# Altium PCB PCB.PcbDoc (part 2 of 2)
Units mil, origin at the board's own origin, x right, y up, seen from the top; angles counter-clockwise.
Board outline 2952.76 x 1850.39 mil, 2 copper layers (Top Layer, Bottom Layer), stack 21 mil thick; 67 components, 133 nets, 435 pads, 333 vias.
Unrouted connection lines stored in the file: 207.
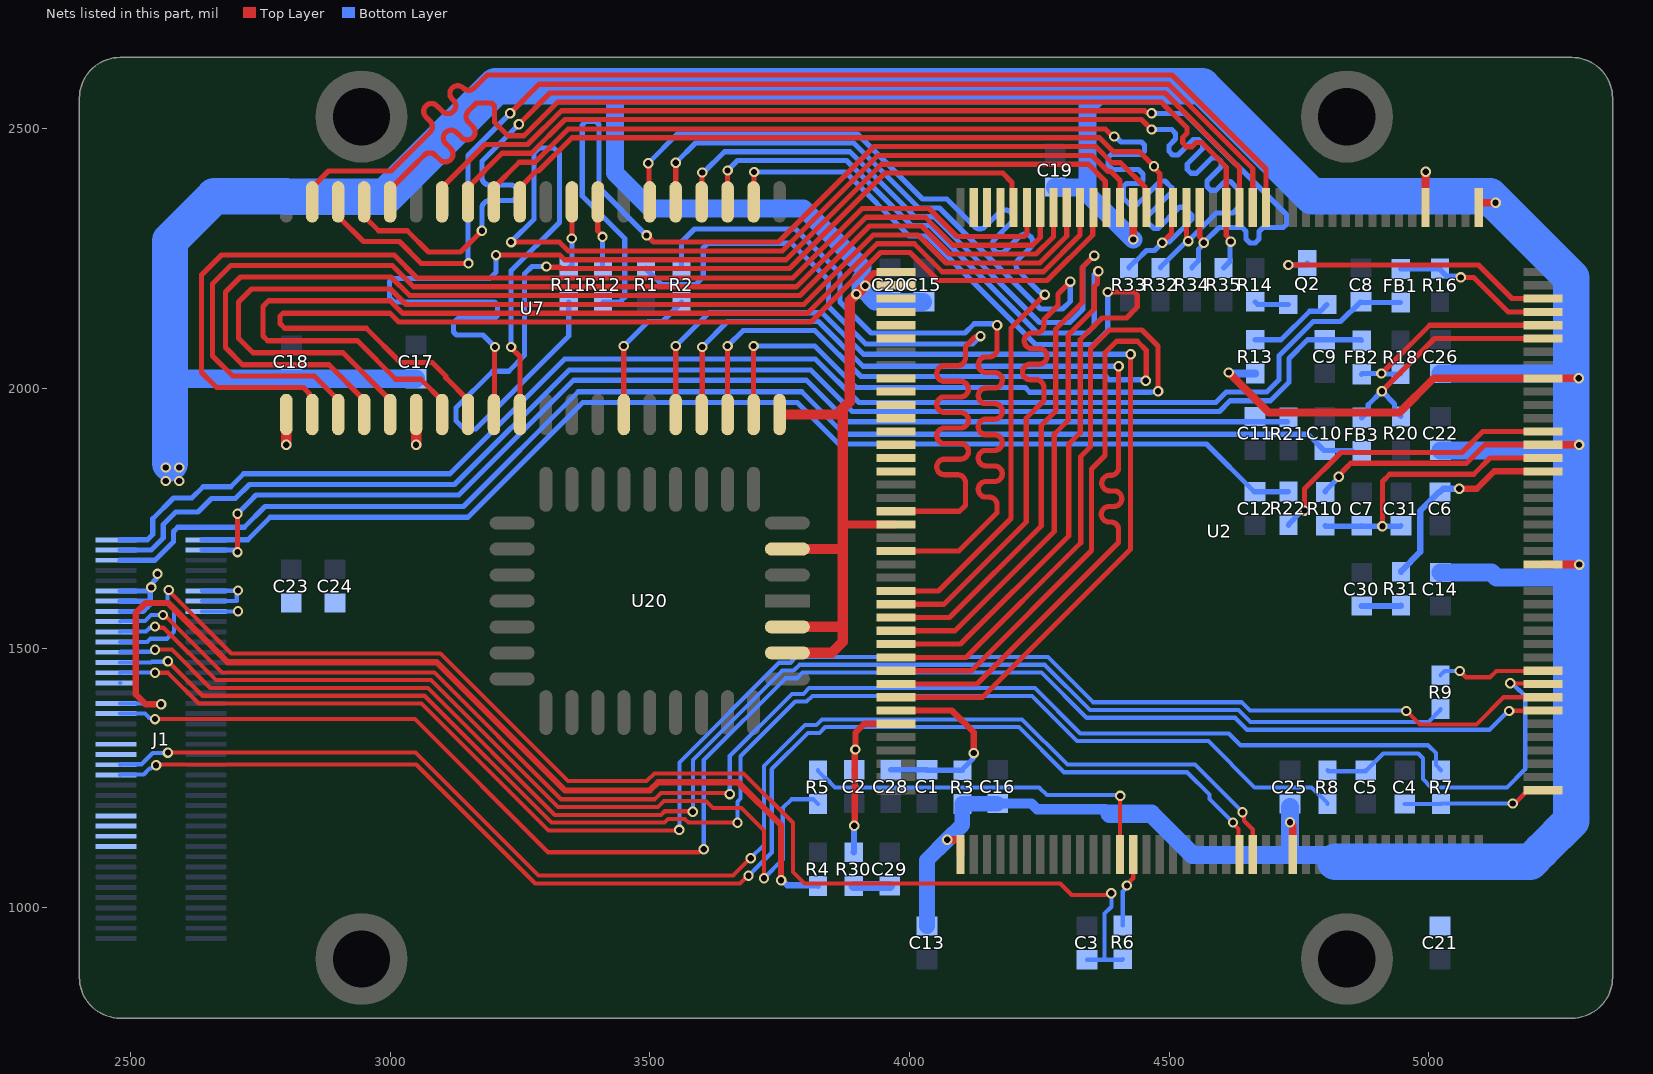
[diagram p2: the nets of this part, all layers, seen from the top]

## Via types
v1: diameter 20, hole 12, Top Layer to Bottom Layer, tented both sides, 331 vias
v2: diameter 27.56, hole 27.56, Top Layer to Bottom Layer, 2 vias

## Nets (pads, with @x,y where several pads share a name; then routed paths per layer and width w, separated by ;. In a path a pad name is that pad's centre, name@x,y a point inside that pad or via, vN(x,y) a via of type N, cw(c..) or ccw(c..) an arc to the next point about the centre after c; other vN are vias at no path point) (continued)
HSYNC1: C11.1 J1.78 R21.2 | length 2305.3
  Top Layer w10: v1(2706,1685) v1(2706,1759)
  Bottom Layer w10: J1.78@2637.8,1688.98 2699.32,1688.98 2703.29,1685 v1(2706,1685) ; v1(2706,1759) 2728.59,1781.59 2742,1795 3132.19,1795 3353.19,2016 3801.81,2016 3881.81,1936 4655.75,1936 R21.2@4727.9,1936
IOCS16#: J1.33 U2.22 | length 2613
  Top Layer w8: v1(2549.35,1274.65) 2550.76,1276.06 3050.37,1276.06 3279.43,1047 3673.89,1047 3688.69,1061.8 v1(3690.2,1061.8) ; v1(4623.29,1164.23) 4623.29,1162.47 4633.99,1151.76 4633.99,1104.2 U2.22@4635.83,1102.36
  Bottom Layer w8: J1.33@2480.31,1255.91 2481.24,1256.83 2525.61,1256.83 2536.79,1268 2539.45,1268 2546.1,1274.65 v1(2549.35,1274.65) ; v1(3690.2,1061.8) 3735,1106.6 3735,1267 3805,1337 3826.96,1337 3837.96,1348 4211,1348 4298,1261 4534.96,1261 4577.98,1217.99 4577.98,1209.54 v1(4623.29,1164.23)
IOR#: J1.55 R8.2 | length 2718.4
  Top Layer w8: v1(2572,1474.88) 2638.42,1408.46 3066.45,1408.46 3310.92,1164 3528.12,1164 3535.12,1171 3567.3,1171 3574.3,1164 v1(3669,1164)
  Bottom Layer w8: J1.55@2480.31,1472.44 2539.73,1472.44 2541.3,1474.02 v1@2571,1474.02 ; v1(3669,1164) 3669,1204.3 3675,1210.3 3675,1291.85 3780.15,1397 3802.11,1397 3813.11,1408 4235.85,1408 4322.85,1321 4576,1321 4665,1232 4774.5,1232 4805,1201.5 R8.2@4805,1200
IORDY: J1.45 U2.47 | length 3153.8
  Top Layer w8: v1(2547.24,1363.46) 3047.81,1363.46 3304.28,1107 3594.75,1107 3600.75,1113 v1(3604,1113) ; v1(5155,1379) 5155.46,1379.46 5220.01,1379.46 U2.47@5220.47,1379.92
  Bottom Layer w8: J1.45@2480.31,1374.02 2528,1374.02 2536.26,1365.76 2544.95,1365.76 v1(2547.24,1363.46) ; v1(3604,1113) 3604,1284.49 3761.51,1442 3783.47,1442 3794.47,1453 4254.49,1453 4341.49,1366 4627.49,1366 4650.49,1343 5117.36,1343 v1@5153.36,1379
IOW#: J1.57 R9.2 | length 2911.5
  Top Layer w8: v1(2547.24,1497.16) 2579.84,1497.16 2653.54,1423.46 3072.67,1423.46 3317.13,1179 3521.91,1179 3528.91,1186 3582,1186 v1(3583,1185)
  Bottom Layer w8: J1.57@2480.31,1492.13 2481.24,1493.05 v1@2548.03,1493.05 ; v1(3583,1185) 3583,1284.71 3755.29,1457 3777.26,1457 3788.26,1468 4260.71,1468 4347.71,1381 4633.71,1381 4656.71,1358 4999.6,1358 5023.1,1381.5 R9.2@5023.1,1383
IREF: Q2.C U2.78 | length 555.5
  Top Layer w10: v1(4730,2238) 5096,2238 5160.77,2173.23 U2.78@5220.47,2173.23
  Bottom Layer w10: v1(4730,2238) 4762.5,2238 Q2.C@4766.5,2242
LA20: J1.25
LA21: J1.23
LA22: J1.21
LA23: J1.19
MCS16#: J1.35 U2.23 | length 2647.2
  Top Layer w8: v1(2572,1299) 3048.64,1299 3285.64,1062 3660.7,1062 v1(3694.35,1095.65) ; v1(4641.51,1184.15) 4643.81,1181.85 4643.81,1173.95 4644.55,1173.21 4644.55,1167.75 4661.21,1151.09 4661.21,1102.57 U2.23@4661.42,1102.36
  Bottom Layer w8: J1.35@2480.31,1275.59 2481.24,1276.51 2521.51,1276.51 2542.9,1297.9 2570.9,1297.9 v1(2572,1299) ; v1(3694.35,1095.65) 3720,1121.3 3720,1273.21 3798.79,1352 3820.75,1352 3831.75,1363 4217.21,1363 4304.21,1276 4550.2,1276 4641.51,1184.69 v1(4641.51,1184.15)
MD0: U2.136
MD1: U2.135
MD2: U2.134
MD3: U2.133
MD4: U2.132
MD5: U2.131
MD6: U2.130
MD7: U2.129
MD8: U2.126
MD9: U2.125
MD10: U2.124
MD11: U2.123
MD12: U2.122
MD13: U2.119
MD14: U2.118
MD15: U2.117
MD16: U2.115 U7.2 | length 2208.3
  Top Layer w10: U7.2@2850,1950 2850,1981.79 2844.41,1987.38 2844.41,1990.59 2833,2002 2666,2002 2637,2031 2637,2219 2675,2257 3008,2257 3052,2213 3775.34,2213 3909.34,2347 4037.6,2347 4091.6,2293 4220.52,2293 4226.38,2298.86 U2.115@4226.38,2348.43
MD17: U2.114 U7.3 | length 2211.2
  Top Layer w10: U7.3@2900,1950 2900,1978 2854,2024 2697,2024 2658,2063 2658,2202 2693,2237 3003.96,2237 3044.96,2196 3782.38,2196 3916.38,2330 4030.56,2330 4084.56,2276 4237.04,2276 4251.97,2290.93 U2.114@4251.97,2348.43
MD18: U2.113 U7.4 | length 2213
  Top Layer w10: U7.4@2950,1950 2950,1978 2882,2046 2716,2046 2683,2079 2683,2186 2712,2215 3001.92,2215 3037.92,2179 3789.42,2179 3923.42,2313 4023.52,2313 4077.52,2259 4244.08,2259 4277.56,2292.48 U2.113@4277.56,2348.43
MD19: U2.112 U7.5 | length 2211
  Top Layer w10: U7.5@3000,1950 3000,1978 2909,2069 2736,2069 2708,2097 2708,2167 2733,2192 3000.88,2192 3030.88,2162 3796.46,2162 3930.46,2296 4016.48,2296 4070.48,2242 4251.12,2242 4303.15,2294.02 U2.112@4303.15,2348.43
MD20: U2.111 U7.7 | length 2228.6
  Top Layer w10: U7.7@3100,1950 3100,1977 3059,2018 3011,2018 2937,2092 2764.25,2092 2755,2101.25 2755,2158.25 2765.75,2169 2999.83,2169 3023.83,2145 3803.5,2145 3937.5,2279 4009.44,2279 4063.44,2225 4258.17,2225 4328.74,2295.57 U2.111@4328.74,2348.43
MD21: U2.110 U7.8 | length 2208.7
  Top Layer w10: U7.8@3150,1950 3150,1978 3107,2021 3107,2024 3081,2050 3020,2050 2954,2116 2797,2116 2788,2125 2788,2139.14 2793.86,2145 2999.79,2145 3016.79,2128 3810.54,2128 3944.54,2262 4001,2262 4055,2208 4265.21,2208 4353.23,2296.02 4353.23,2347.33 U2.110@4354.33,2348.43
MD22: U2.109 U7.9 | length 2159.7
  Top Layer w10: U7.9@3200,1950 3201,1951 3201,2079 v1(3202,2080) ; v1(3204,2257) 3326.85,2257 3335.85,2248 3762.25,2248 3946.25,2432 4344.76,2432 4377.05,2399.72 4377.05,2351.3 U2.109@4379.92,2348.43
  Bottom Layer w10: v1(3202,2080) 3178.86,2103.14 3127.86,2103.14 3122,2109 3122,2126 3131,2135 3201.14,2135 3207,2140.86 3207,2161 3201,2167 3008,2167 2999,2176 2999,2206.14 3004.86,2212 3192,2212 3204,2224 v1(3204,2257)
MD23: U2.108 U7.10 | length 2123.4
  Top Layer w10: v1(3233,2080) 3233,2078.64 3250,2061.64 U7.10@3250,1950 ; v1(3233,2282) 3325.89,2282 3342.89,2265 3755.21,2265 3939.21,2449 4351.8,2449 4382.8,2418 4388.34,2418 4405.51,2400.83 U2.108@4405.51,2348.43
  Bottom Layer w10: v1(3233,2080) 3233,2227 3326,2320 3326,2452.4 3315,2463.4 3287,2463.4 3277,2453.4 3277,2326 v1(3233,2282)
MD24: U2.105 U7.31 | length 1395.6
  Top Layer w10: U7.31@3250,2359.45 3250,2387.45 3281.55,2419 3286,2419 3350,2483 4365.89,2483 4392.89,2456 4443,2456 v1(4471,2428) 4471,2425.29 4482.28,2414.01 U2.105@4482.28,2348.43
MD25: R33.2 U2.104 U7.32 | length 2161.7
  Top Layer w10: U7.32@3200,2359.45 3200,2387.45 3248.55,2436 3278.96,2436 3342.96,2500 4377.29,2500 4391.79,2485.5 v1(4394.5,2485.5) ; v1(4487,2281) 4505,2299 4505,2345.55 U2.104@4507.87,2348.43
  Bottom Layer w10: v1(4394.5,2485.5) 4397.21,2485.5 4407.71,2475 4447.14,2475 4453,2469.14 4453,2456.86 4447.14,2451 4388.86,2451 4383,2445.14 4383,2430 4391,2422 4441,2422 4450,2413 4450,2400.86 4444.14,2395 4417.86,2395 4412,2389.14 4412,2367 4424,2355 4439,2355 4483.86,2399.86 4492.14,2399.86 4505.36,2386.64 4505.36,2378.36 4457.14,2330.14 4457.14,2321.86 4470.86,2308.14 4479.14,2308.14 4520.36,2349.36 4528.64,2349.36 4543.86,2334.14 4543.86,2325.86 4500.68,2282.68 4488.68,2282.68 4471.82,2265.82 4456.82,2265.82 4437,2246 4435.5,2246 4423,2233.5 R33.2@4423,2232
MD26: R32.2 U2.103 U7.33 | length 2160.8
  Top Layer w10: U7.33@3150,2359.45 3150,2387.45 3215.55,2453 3271.92,2453 3336.92,2518 4447,2518 4466.11,2498.89 v1(4466.5,2498.89) ; U2.103@4533.46,2348.43 4533.46,2290.24 4537,2286.71 v1(4537,2284)
  Bottom Layer w10: v1(4466.5,2498.89) 4488.45,2498.89 4505.27,2498.89 4512.77,2491.39 4512.77,2480.78 4499.76,2467.77 4499.76,2457.17 4506.83,2450.1 4517.44,2450.1 4546.85,2479.5 4557.45,2479.5 4564.52,2472.43 4564.52,2461.83 4535.11,2432.42 4535.11,2421.81 4542.19,2414.74 4552.79,2414.74 4582.2,2444.15 4592.81,2444.15 4599.88,2437.08 4599.88,2426.47 4573.04,2399.63 4573.04,2389.02 4580.11,2381.95 4590.72,2381.95 4607.58,2398.81 4618.19,2398.81 4635,2382 4635,2366 4635,2350 4623,2338 4591,2338 v1(4537,2284) 4535.09,2282.09 4532.34,2282.09 4483.75,2233.5 R32.2@4483.75,2232
MD27: R34.2 U2.102 U7.34 | length 2160.8
  Top Layer w10: U7.34@3100,2359.45 3100,2387.45 3182.55,2470 3264.88,2470 3329.88,2535 4454.04,2535 4457.13,2531.91 4464.59,2531.91 v1(4466.5,2530) ; U2.102@4559.06,2348.43 4559.06,2291.65 4567,2283.71 v1(4567,2281)
  Bottom Layer w10: v1(4466.5,2530) 4531,2530 4726,2335 4726,2315.86 4720.14,2310 4686,2310 4681,2310 4673.5,2302.5 4673.5,2288.1 4666,2280.6 4656,2280.6 4648.5,2288.1 4648.5,2302.5 4641,2310 4628,2310 4596,2310 v1(4567,2281) 4567,2278.29 4557,2268.29 4557,2246 4544.5,2233.5 R34.2@4544.5,2232
MD28: R35.2 U2.100 U7.36 | length 2187.8
  Top Layer w10: U7.36@3000,2359.45 3000,2383.66 3041.01,2424.67 3065.76,2449.42 cw(c3076.37,2438.81) 3086.97,2449.42 3095.52,2440.87 ccw(c3106.13,2451.48) 3116.73,2440.87 ccw(c3106.13,2451.48) 3116.73,2462.08 3106.76,2472.06 cw(c3117.36,2482.67) 3106.76,2493.27 cw(c3117.36,2482.67) 3127.97,2493.27 3137.95,2483.3 ccw(c3148.55,2493.9) 3159.16,2483.3 ccw(c3148.55,2493.9) 3159.16,2504.51 3150.61,2513.06 cw(c3161.22,2523.67) 3150.61,2534.27 3166.34,2550 3167.46,2550 3195.14,2550 3201,2544.14 3201,2513 3227,2487 3257.83,2487 3322.83,2552 4485,2552 4492.56,2544.44 4513.5,2523.5 4534.71,2502.29 4534.71,2491.68 4526.31,2483.28 4526.31,2472.67 4533.38,2465.6 4543.99,2465.6 4552.39,2474 4563,2474 4599.5,2437.5 4610.24,2426.76 4610.24,2399.45 U2.100@4610.24,2348.43 4610.12,2348.31 4610.12,2294.59 4619,2285.71 v1(4619,2283)
  Bottom Layer w10: R35.2@4605.25,2232 4617.75,2244.5 4617.75,2281.75 v1(4619,2283)
MD29: U2.99 U7.37 | length 2197.4
  Top Layer w10: U7.37@2950,2359.45 2950,2332 2978,2304 3033,2304 3074,2263 3135.72,2263 v1(3176.72,2304) ; v1(3248,2509) 3308,2569 4492.04,2569 4635.83,2425.21 U2.99@4635.83,2348.43
  Bottom Layer w10: v1(3176.72,2304) 3176.72,2312 3176.72,2347 cw(c3191.72,2347) 3191.72,2362 3231.64,2362 ccw(c3231.64,2377) 3231.64,2392 3191.72,2392 cw(c3191.72,2407) 3176.72,2407 3176.72,2437.72 3217,2478 v1(3248,2509)
MD30: U2.98 U7.38 | length 2235.5
  Top Layer w10: U7.38@2900,2359.45 2900,2331.45 2948.45,2283 3018,2283 3060,2241 v1(3151,2241) ; v1(3231,2530) 3287,2586 3388.04,2586 4499.08,2586 4661.42,2423.67 U2.98@4661.42,2348.43
  Bottom Layer w10: v1(3151,2241) 3150,2242 3150,2449 v1(3231,2530)
MD31: U2.97 U7.39 | length 2202.6
  Top Layer w10: U7.39@2850,2359.45 2850,2387.45 2881.55,2419 3002,2419 3073.5,2490.5 3077.04,2494.04 ccw(c3066.43,2504.64) 3077.04,2515.25 3069.04,2523.25 cw(c3079.64,2533.85) 3069.04,2544.46 cw(c3079.64,2533.85) 3090.25,2544.46 3100.8,2533.91 ccw(c3111.4,2544.52) 3122.01,2533.91 ccw(c3111.4,2544.52) 3122.01,2555.13 3119.46,2557.68 cw(c3130.07,2568.28) 3119.46,2578.89 cw(c3130.07,2568.28) 3140.67,2578.89 ; 3140.68,2578.89 ccw(c3151.28,2589.5) 3161.89,2578.89 3187,2604 3190,2604 4506,2604 4687.01,2422.99 U2.97@4687.01,2348.43
MEMR#: J1.39
MEMW#: J1.37
NetC1_1: C1.1 C28.1 R3.2 U2.154 | length 387.1
  Top Layer w12: U2.154@3974.41,1379.92 4082.08,1379.92 4124,1338 v1(4124,1298)
  Bottom Layer w10: C28.1@3964,1266 C1.1@4034,1266 ; C1.1@4034,1265 R3.2@4102,1265 4102,1266.5 4122.09,1286.59 4122.09,1296.09 v1(4124,1298)
NetC2_1: C2.1 R30.1 U2.155 | length 356.7
  Top Layer w12: v1(3894,1158) 3895,1159 3895,1304 v1(3896,1305) 3896,1337 3913.33,1354.33 U2.155@3974.41,1354.33
  Bottom Layer w10: C2.1@3894,1266 3896,1268 v1(3896,1305)
  Bottom Layer w12: R30.1@3893,1107 3893.5,1107.5 3893.5,1157.5 v1(3894,1158)
NetC4_1: C4.1 R7.2 U2.41 | length 277.4
  Top Layer w8: v1(5162,1201) 5164.3,1203.3 5167.86,1203.3 5190.94,1226.38 U2.41@5220.47,1226.38
  Bottom Layer w8: C4.1@4954,1200 R7.2@5024,1200 5025,1201 v1(5162,1201)
NetC5_1: C5.1 R8.1 U2.49 | length 700.9
  Top Layer w8: v1(5157.11,1432.69) 5157.9,1431.89 5219.68,1431.89 U2.49@5220.47,1431.1
  Bottom Layer w8: R8.1@4805,1265 4807,1263 C5.1@4879,1263 ; C5.1@4879,1264.96 4880.5,1264.96 4912.54,1297 4980,1297 4989,1288 4989,1247.94 5004.94,1232 5151,1232 5186,1267 5186,1408 5174.92,1419.08 5173.96,1419.08 v1@5160.35,1432.69
NetC6_1: C6.1 R31.1 U2.65 | length 400.8
  Top Layer w12: v1(5059,1807) 5093,1807 5126.55,1840.55 U2.65@5220.47,1840.55
  Bottom Layer w12: R31.1@4947,1647 4947,1648.5 4984,1685.5 4984,1764.46 5020.5,1800.96 C6.1@5022,1800.96 5028.04,1807 v1(5059,1807)
NetC7_1: C7.1 C31.1 R10.1 U2.66 | length 561.4
  Top Layer w10: v1(4911,1735) 4911,1821 4925,1835 5087,1835 5118.14,1866.14 U2.66@5220.47,1866.14
  Bottom Layer w10: R10.1@4801,1736 4802,1735 4870,1735 C7.1@4871,1736 ; C7.1@4871,1735 4946,1735 C31.1@4947,1736
NetC29_1: C29.1 R30.2 | length 69
  Bottom Layer w19.68: R30.2@3893,1042 C29.1@3962,1042
NetC30_1: C30.1 R31.2 | length 76.4
  Bottom Layer w12: C30.1@4871,1581.04 4946.04,1581.04 R31.2@4947,1582
NetQ2_B: Q2.B R13.1 | length 166.7
  Bottom Layer w10: R13.1@4666,2093.97 4715.97,2093.97 4771,2149 4791.5,2149 Q2.B@4804.5,2162
NetQ2_E: Q2.E R14.2 | length 65.6
  Bottom Layer w10: R14.2@4666,2167 4671,2162 Q2.E@4729.5,2162
NetR1_2: R1.2 U2.139 | length 1695.6
  Top Layer w10: U2.139@3974.41,1763.78 4096.78,1763.78 4108,1775 4108,1814 4108,1819 ccw(c4093,1819) 4093,1834 4067.69,1834 cw(c4067.69,1849) 4067.69,1864 4098.69,1864 ccw(c4098.69,1879) 4098.69,1894 4067.69,1894 cw(c4067.69,1909) 4067.69,1924 4098.69,1924 ccw(c4098.69,1939) 4098.69,1954 4067.69,1954 cw(c4067.69,1969) 4067.69,1984 4098.69,1984 ccw(c4098.69,1999) 4098.69,2014 4067.69,2014 cw(c4067.69,2029) 4067.69,2044 4093,2044 ccw(c4093,2059) 4108,2059 4108,2080.93 4116.78,2089.71 4126.16,2099.09 4135.09,2099.09 v1(4137,2101)
  Bottom Layer w10: R1.2@3493,2232 3493,2230.5 3523.5,2200 3588,2200 3603,2215 3603,2271 3612,2280 3773,2280 3844,2209 3844,2157.96 3915.96,2086 4122,2086 v1(4137,2101)
NetR2_2: R2.2 U2.142 | length 1693.9
  Top Layer w10: U2.142@3974.41,1687.01 4095.01,1687.01 4169,1761 4169,1770.98 4169,1775.98 ccw(c4154,1775.98) 4154,1790.98 4147.54,1790.98 cw(c4147.54,1805.98) 4147.54,1820.98 4164,1820.98 ccw(c4164,1835.98) 4164,1850.98 4147.54,1850.98 cw(c4147.54,1865.98) 4147.54,1880.98 4164,1880.98 ccw(c4164,1895.98) 4164,1910.98 4147.54,1910.98 cw(c4147.54,1925.98) 4147.54,1940.98 4164,1940.98 ccw(c4164,1955.98) 4164,1970.98 4147.54,1970.98 cw(c4147.54,1985.98) 4147.54,2000.98 4164,2000.98 ccw(c4164,2015.98) 4164,2030.98 4147.54,2030.98 cw(c4147.54,2045.98) 4147.54,2060.98 4154,2060.98 ccw(c4154,2075.98) 4169,2075.98 4169,2119.77 v1(4169,2122)
  Bottom Layer w10: R2.2@3561,2232 3561,2282 3586,2307 3781,2307 3866.5,2221.5 3866.5,2166.5 3926,2107 4107.29,2107 4125,2124.71 4159.22,2124.71 4160.02,2123.91 4167.09,2123.91 v1(4169,2122)
NetR5_2: R5.2 U2.13 | length 716.7
  Top Layer w8: U2.13@4405.51,1102.36 4405.76,1102.61 4405.76,1215.26 v1(4406,1215.5)
  Bottom Layer w8: R5.2@3824,1265 3824,1263.5 3837.5,1250 3839,1250 3857,1232 4250,1232 4265,1217 4404.5,1217 v1(4406,1215.5)
NetR6_2: R6.2 U2.14 | length 144.7
  Top Layer w8: v1(4419,1043) 4419,1044.95 4431.1,1057.05 U2.14@4431.1,1102.36
  Bottom Layer w8: R6.2@4411,966 4411,1031.75 4419,1039.75 v1(4419,1043)
NetR9_1: R9.1 U2.50 | length 210.9
  Top Layer w8: v1(5060,1456) 5072,1444 5118,1444 5130.35,1456.35 5220.13,1456.35 U2.50@5220.47,1456.69
  Bottom Layer w8: R9.1@5023.1,1448 5031.1,1456 v1(5060,1456)
NetR11_1: R11.1 U2.116 | length 1799.5
  Top Layer w10: v1(3301,2235) 3302.2,2233.8 3326,2233.8 3328.8,2231 3769.29,2231 3953.29,2415 4180,2415 4197.91,2397.09 4197.91,2351.3 U2.116@4200.79,2348.43
  Bottom Layer w10: v1(3301,2235) 3273,2235 3259,2221 3259,2064 3228.49,2033.49 3197.49,2033.49 3126.91,1962.91 3126.91,1938.09 3142.91,1922.09 3165.09,1922.09 3344,2101 R11.1@3344,2167
NetR12_1: R12.1 U2.106 | length 1814.9
  Top Layer w10: v1(3494,2295) 3507,2282 3748.17,2282 3932.17,2466 4358.85,2466 4389.85,2435 4406.77,2435 4453.82,2387.95 4453.82,2351.3 U2.106@4456.69,2348.43
  Bottom Layer w10: R12.1@3410,2167 3443,2167 3452,2176 3452,2289 3370,2371 3370,2507.71 3376.86,2514.57 3396,2514.57 3402,2508.57 3402,2387 v1(3494,2295)
OSC: J1.47 R4.1 | length 1917.1
  Top Layer w12: v1(2559,1392) 2529,1392 2510,1411 2510,1568 2529.02,1587.02 2572.94,1587.02 2686.96,1473 3089.6,1473 3336.6,1226 3500,1226 3516,1242 3670,1242 3753,1159 v1(3753,1053)
  Bottom Layer w8: J1.47@2480.31,1393.7 2531.88,1393.7 2533,1392.58 2558.42,1392.58 v1(2559,1392)
  Bottom Layer w12: v1(3753,1053) 3755.16,1053 3764.66,1043.5 3824,1043.5 R4.1@3824,1042
RAS#: R2.1 U7.14 | length 279.1
  Top Layer w10: U7.14@3450,1950 v1(3450,2082)
  Bottom Layer w10: v1(3450,2082) 3497,2129 3524.5,2129 3561,2165.5 R2.1@3561,2167
REFSH#: J1.53 U2.48 | length 3158.4
  Top Layer w8: v1(2547.24,1452.6) 2572.4,1452.6 2631.54,1393.46 3060.24,1393.46 3304.71,1149 v1@3557,1149 ; v1(4957,1379) 4983,1353 5092,1353 5144.51,1405.51 U2.48@5220.47,1405.51
  Bottom Layer w8: J1.53@2480.31,1452.76 2480.44,1452.89 2549.87,1452.89 v1@2550,1453.02 ; v1(3557,1150) 3557,1279.92 3749.08,1472 3771.04,1472 3782.04,1483 4266.92,1483 4353.92,1396 4639.92,1396 4655.92,1380 4956,1380 v1(4957,1379)
RESET: J1.63 R7.1 | length 2908
  Top Layer w8: v1(2562.64,1563.92) 2565.88,1563.92 2676.33,1453.46 3085.09,1453.46 3329.56,1209 3509.48,1209 3521.48,1221 3652,1221 v1(3654,1219)
  Bottom Layer w8: J1.63@2480.31,1551.18 2481.24,1552.1 2527.92,1552.1 2539.73,1563.92 v1(2562.64,1563.92) ; v1(3654,1219) 3654,1292.07 3773.93,1412 3795.9,1412 3806.9,1423 4242.07,1423 4329.07,1336 4615.07,1336 4638.07,1313 4999,1313 5014,1298 5014,1275 R7.1@5024,1265
SMEMR#: C3.1 J1.59 R6.1 | length 2529.8
  Top Layer w8: v1(2573.9,1612) 2573.9,1610.1 2694,1490 3096.64,1490 3342.64,1244 3493.96,1244 3508.96,1259 3680.79,1259 3776,1163.79 3776,1095 3776,1068.79 3797.79,1047 3824,1047 4290.64,1047 4312.64,1025 4378.31,1025 4379.02,1025.7 4386.7,1025.7 v1(4389,1028)
  Bottom Layer w8: J1.59@2480.31,1511.81 2532.19,1511.81 2538.55,1518.16 2570.16,1518.16 2583.64,1531.64 2583.64,1573.17 2570.95,1585.86 2570.95,1592.49 2571.6,1593.14 2571.6,1609.7 v1(2573.9,1612) ; C3.1@4342,900 4376,900 ; v1(4389,1028) 4389,1002 4376,989 4376,900 ; R6.1@4411,901 4410,900 4376,900
SMEMW#: J1.61 R5.1 | length 1738
  Top Layer w8: v1(2547.24,1541.73) 2549.54,1539.44 2563.56,1539.44 2664.54,1438.46 3078.88,1438.46 3323.35,1194 3515.69,1194 3527.69,1206 3608,1206 3622,1192 3676.53,1192 3720,1148.53 v1(3720,1057)
  Bottom Layer w8: J1.61@2480.31,1531.5 2481.24,1532.42 2530.17,1532.42 2537.19,1539.44 2548.42,1539.44 v1@2549,1540.02 ; v1(3720,1057) 3756,1093 3756,1192 3773,1209 3815,1209 R5.1@3824,1200
SYSCLK: J1.51 | length 0
VA0: U2.153 U7.16 | length 2012.8
  Top Layer w10: U7.16@3550,1950 v1(3550,2082) ; U2.153@3974.41,1405.51 4141.04,1405.51 4426,1690.48 v1(4426,2066)
  Bottom Layer w10: v1(3550,2082) 3614,2146 3831.92,2146 3911.92,2066 v1(4426,2066)
VA1: U2.152 U7.17 | length 1962.8
  Top Layer w10: U7.17@3601,1948 v1(3601,2080) ; U2.152@3974.41,1431.1 4130.44,1431.1 4403,1703.67 4403,1723 4403,1728 ccw(c4388,1728) 4388,1743 4384.62,1743 cw(c4384.62,1758) 4384.62,1773 4394,1773 ccw(c4394,1788) 4394,1803 4385.61,1803 cw(c4385.61,1818) 4385.61,1833 4388,1833 ccw(c4388,1848) 4403,1848 4403,2022 v1(4403,2043)
  Bottom Layer w10: v1(3601,2080) 3650,2129 3824.88,2129 3910.88,2043 v1(4403,2043)
VA2: U2.151 U7.18 | length 2008.4
  Top Layer w10: U7.18@3650,1950 v1(3650,2082) ; U2.151@3974.41,1456.69 4119.84,1456.69 4351,1687.86 4351,1845 4377,1871 4377,2069 4399,2091 4439,2091 4456,2074 4456,2016 v1(4455,2015)
  Bottom Layer w10: v1(3650,2082) 3680,2112 3817.83,2112 3906.83,2023 4379,2023 4385.09,2016.91 4453.09,2016.91 v1(4455,2015)
VA3: U2.150 U7.19 | length 2022.3
  Top Layer w10: U7.19@3700,1950 v1(3700,2082) ; U2.150@3974.41,1482.28 4109.24,1482.28 4330,1703.05 4330,1869 4349,1888 4349,2077 4385,2113 4448,2113 4479,2082 v1(4479,1995)
  Bottom Layer w10: v1(3700,2082) 3817.84,2082 3897.84,2002 4223,2002 4232,1993 4464.29,1993 4464.38,1993.09 4477.09,1993.09 v1(4479,1995)
VA4: U2.149 U7.22 | length 1986.1
  Top Layer w10: U7.22@3700,2359.45 3700.5,2359.95 3700.5,2416.5 v1(3701,2417) ; U2.149@3974.41,1507.87 4098.64,1507.87 4307,1716.24 4307,1893 4329,1915 4329,2094 4371,2136 4418,2136 4439,2157 4439,2180.14 4433.14,2186 v1(4382,2186)
  Bottom Layer w10: v1(3701,2417) 3876.83,2417 3999.83,2294 4034,2294 4243,2085 4355,2085 4382,2112 v1(4382,2186)
VA5: U2.148 U7.23 | length 1947.4
  Top Layer w10: U7.23@3650,2359.45 v1(3650,2420) ; U2.148@3974.41,1533.47 4088.04,1533.47 4279,1724.43 4279,1912 4306,1939 4306,2103 4356,2153 4356,2196 4362.09,2202.09 4362.09,2224.09 v1(4364,2226)
  Bottom Layer w10: v1(3650,2420) 3669,2439 3878.88,2439 4003.92,2313.96 4039.77,2313.96 4246.72,2107 4342,2107 4356,2121 4356,2219.57 4362.43,2226 v1(4364,2226)
VA6: U2.147 U7.24 | length 1981.6
  Top Layer w10: U7.24@3600,2359.45 3600.5,2359.95 3600.5,2415.5 v1(3601,2416) ; U2.147@3974.41,1559.06 4077.44,1559.06 4254,1735.62 4254,1929 4282,1957 4282,2115 4333,2166 4333,2233 v1(4356,2256)
  Bottom Layer w10: v1(3601,2416) 3603.71,2416 3643.71,2456 3885.92,2456 4010.96,2330.96 4046.81,2330.96 4250.76,2127 4309,2127 4334,2152 4334,2234 v1(4356,2256)
VA7: U2.146 U7.25 | length 1960.8
  Top Layer w10: U7.25@3550,2359.45 v1(3550,2435) ; U2.146@3974.41,1584.65 4066.84,1584.65 4225,1742.81 4225,1943 4259,1977 4259,1997 4259,2002 ccw(c4244,2002) 4244,2017 4232.95,2017 cw(c4232.95,2032) 4232.95,2047 4250,2047 ccw(c4250,2062) 4250,2077 4236.17,2077 cw(c4236.17,2092) 4236.17,2107 4244,2107 ccw(c4244,2122) 4259,2122 4259,2133 4286,2160 4286,2182 v1(4310,2206)
  Bottom Layer w10: v1(3550,2435) 3588,2473 3892.96,2473 4018,2347.96 4057.81,2347.96 4252.76,2153 4295,2153 4310,2168 v1(4310,2206)
VA8: U2.145 U7.26 | length 1951.3
  Top Layer w10: v1(3497,2434) 3498.5,2432.5 3498.5,2360.95 U7.26@3500,2359.45 ; U2.145@3974.41,1610.24 4056.24,1610.24 4196,1750 4196,2116 v1(4261,2181)
  Bottom Layer w10: v1(3497,2434) 3553,2490 3900,2490 4025.04,2364.96 4071.92,2364.96 4121.44,2315.44 4124.97,2311.9 ccw(c4135.58,2322.51) 4146.19,2311.9 4173.73,2339.45 cw(c4184.34,2328.84) 4194.95,2339.45 cw(c4184.34,2328.84) 4194.95,2318.23 4163.86,2287.15 ccw(c4174.47,2276.55) 4163.86,2265.94 ccw(c4174.47,2276.55) 4185.08,2265.94 4212.11,2292.98 cw(c4222.72,2282.37) 4233.33,2292.98 cw(c4222.72,2282.37) 4233.33,2271.76 4209.83,2248.26 ccw(c4220.43,2237.66) 4209.83,2227.05 4250.88,2186 4253.29,2186 4254.62,2184.68 4258.29,2181 v1(4261,2181)
VCC: C13.1 C14.1 C15.1 C16.1 C17.1 C18.1 C19.1 C20.1 C21.1 C22.1 C23.1 C24.1 C25.1 C26.1 J1.65 J1.66 J1.67 J1.68 J1.69 J1.70 R3.1 R10.2 R13.2 U2.1 U2.26 U2.58 U2.67 U2.72 U2.81 U2.85 U2.107 U2.121 U2.140 U7.1 U7.6 U7.20 U20.3 U20.31 U20.32 | length 12322.5
  Top Layer w10: v1(4827,1830) 4827,1832.71 4842.93,1848.63 4842.93,1848.93 4850,1856 5073,1856 5108.73,1891.73 U2.67@5220.47,1891.73 ; U2.58@5220.47,1661.42 U2.58@5220.68,1661.21 ; v1@5289.79,1661.21 v1(5290,1661)
  Top Layer w12: v1@3915.83,2201.7 3916.53,2201.7 3919,2204.16 3919,2210 3931.53,2222.53 3972.54,2222.53 U2.121@3974.41,2224.41
  Top Layer w15: 3872,1736 3874.19,1738.19 U2.140@3974.41,1738.19 ; v1(4073,1131) 4098.05,1131 4098.43,1130.63 U2.1@4098.43,1102.36 ; v1(4431,2287) 4431.05,2287.05 U2.107@4431.1,2348.43 U2.107@4431.1,2348.43 ; v1(4615,2031) 4692,1954 4944,1954 5009.68,2019.69 U2.72@5220.47,2019.69 5220.63,2019.84 5288.84,2019.84 v1(5289,2020) ; v1(4733,1165) 4733,1163.65 4738.19,1158.46 U2.26@4738.19,1102.36 ; U2.85@4994.09,2348.43 v1@4994.09,2417.54 ; U2.81@5096,2359 5097,2358 v1(5129,2358) ; U2.67@5220.47,1891.73 v1@5289.58,1891.73 ; U2.58@5220.68,1661.21 v1@5289.79,1661.21
  Top Layer w20: v1(2800,1892) U7.1@2800,1950 ; v1(3050,1892) U7.6@3050,1950 ; U7.20@3750,1950 3860.28,1950 3872,1961.72 ; U20.31@3765,1491 3850.28,1491 3872,1512.72 3872,1538 ; U20.32@3765,1541 3869,1541 3872,1538 ; U20.3@3765,1691 3866,1691 3872,1697 ; v1(3915,2198) 3899,2182 v1(3898,2182) 3885,2169 3885,1974.72 3872,1961.72 ; 3872,1538 3872,1697 ; 3872,1697 3872,1736 3872,1961.72
  Bottom Layer w8: J1.66@2637.8,1570.87 2637.86,1570.93 2706.93,1570.93 v1(2707,1571) ; J1.68@2637.8,1590.55 2704.31,1590.55 2704.7,1590.94 2704.7,1608.7 v1@2706.62,1610.62 ; J1.70@2637.8,1610.24 2638.18,1610.62 v1@2706.62,1610.62 ; v1(2707,1611) v1@2706.62,1610.62
  Bottom Layer w10: J1.65@2480.31,1570.87 2524.05,1570.87 2531.92,1578.73 2532.23,1578.73 2538.09,1584.59 2538.09,1591 ; J1.67@2480.31,1590.55 2537.64,1590.55 2538.09,1591 ; J1.69@2480.31,1610.24 2531.53,1610.24 v1@2539.15,1617.85 ; v1(2552,1643) 2550.09,1641.09 2550.09,1634.09 2544.18,1628.18 2544.18,1628.04 2541.91,1625.77 2541.91,1618.91 v1(2540,1617) 2538.09,1615.09 2538.09,1591 ; R10.2@4801,1801 4801,1802.5 4827,1828.5 v1(4827,1830)
  Bottom Layer w12: v1(3915,2198) 3916.53,2199.53 3916.53,2230.53 3919,2233
  Bottom Layer w15: v1(4615,2031) 4616.35,2031 4618.38,2028.97 R13.2@4666,2028.97 ; C25.1@4733,1184.4 C25.1@4733,1200 ; 4994.3,2370.38 v1(4994.3,2417.74)
  Bottom Layer w20: R3.1@4102,1200 R3.1@4102.5,1200.5 ; C16.1@4169.5,1200.5 C16.1@4170,1201.04 4235,1201 4246,1190 4377,1190 4386,1181
  Bottom Layer w30: C13.1@4034,964.96 4034,1092 v1(4073,1131) 4102,1160 R3.1@4102,1200 ; R3.1@4102.5,1200.5 C16.1@4169.5,1200.5
  Bottom Layer w35: v1@2571,1850 v1@2589,1850 ; 2576,2021 2577.98,2019.02 C18.1@2810,2019.02 C17.1@3050,2019.02 ; 2799,2369.08 2800,2370.08 ; 3460,2582 3433,2555 3433,2415 3501,2347 3796,2347 3891.04,2251.96 3910,2233 ; 3906,2209.5 3906,2193 3909.5,2189.5 3912.5,2189.5 3933.96,2168.04 3961.61,2168.04 C20.1@3962.65,2167.04 C15.1@4026.5,2167 ; 4147.04,2580.04 4149,2582 ; C19.1@4281,2388 4282,2387 4331,2387 4343,2375 ; 4383,2582 4343,2542 4343,2375 ; 4386,1181 4466,1181 4545,1102 4733,1102 ; v1(4431,2287) 4343,2375 ; C25.1@4733,1194 v1(4733,1165) 4733,1102 ; 4820,1089 4807,1102 4733,1102 ; C14.1@5022.75,1646 5121,1646 5131,1636 5269,1636 ; C22.1@5023,1881 5265,1881 5275,1871 ; C26.1@5023,2029 5264,2029 5274,2019
  Bottom Layer w70: 2576,1856 2576,2021 2576,2284.66 2661.42,2370.08 2800,2370.08 ; 2799,2369.08 2990.08,2369.08 3203,2582 3435,2582 3460,2582 4149,2582 4383,2582 4432,2582 4564,2582 4775.92,2370.08 4878.9,2370.08 4994.3,2370.08 5118.11,2370.08 ; 4820,1089 5196,1089 5217,1110 5275,1168 5275,1636 5275,1871 5275,2019 5275,2213.19 5118.11,2370.08 ; v1(5129,2358) 5129,2359.19 5118.11,2370.08
  other v1: 2568,1822 2594,1822 2568,1848 2594,1848 5289.79,1891.52
VGA_B: FB3.2 R20.2 U2.75 | length 484.4
  Top Layer w10: v1(4910,1995) 5011.46,2096.46 U2.75@5220.47,2096.46
  Bottom Layer w10: FB3.2@4871,1943.57 4883.72,1956.28 4883.72,1968.72 v1(4910,1995) 4934.5,1970.5 4934.5,1958.5 R20.2@4947,1946
VGA_B1: C10.1 FB3.1 J1.75 | length 2566.1
  Bottom Layer w10: J1.75@2480.31,1669.29 2547.29,1669.29 2583,1705 2583,1725 2591,1733 2719,1733 2759,1773 3141.3,1773 3362.3,1994 3792.7,1994 3874.7,1912 4767.5,1912 4798.5,1881 C10.1@4800,1881 4852,1881 4853,1880
VGA_G: FB2.2 R18.2 U2.76 | length 425.5
  Top Layer w10: v1(4909,2029) 5002.05,2122.05 U2.76@5220.47,2122.05
  Bottom Layer w10: FB2.2@4871,2027.72 4872.28,2029 v1(4909,2029) ; v1@4909,2028 R18.2@4946,2028
VGA_G1: C9.1 FB2.1 J1.77 | length 2667.6
  Bottom Layer w10: J1.77@2480.31,1688.98 2539.98,1688.98 2563,1712 2563,1738 2587,1762 2630,1762 2656,1788 2701.9,1788 2728.9,1815 3123.9,1815 3344.9,2036 3810.1,2036 3890.1,1956 4597,1956 4617.46,1976.46 4695.46,1976.46 4731,2012 4731,2058 4766.98,2093.98 C9.1@4800,2093.98 4869.3,2093.98 FB2.1@4871,2092.28
VGA_R: FB1.2 R16.2 U2.77 | length 310.2
  Top Layer w10: v1(5062,2214) 5087,2214 5153.36,2147.64 U2.77@5220.47,2147.64
  Bottom Layer w10: FB1.2@4946,2230.28 5021.28,2230.28 R16.2@5022,2231 5022,2229.5 5034.5,2217 5056.29,2217 5059.29,2214 v1(5062,2214)
VGA_R1: C8.1 FB1.1 J1.79 | length 2770.5
  Bottom Layer w10: J1.79@2480.31,1708.66 2533,1708.66 2543,1718.66 2543,1749.23 2582.77,1789 2618,1789 2640,1811 2693.06,1811 2718.06,1836 3115.21,1836 3336.21,2057 3818.79,2057 3902.79,1973 4589.96,1973 4610.42,1993.46 4688.42,1993.46 4712,2017.04 4712,2063.04 4777.96,2129 4830.5,2129 4868.5,2167 C8.1@4870,2167 4871.28,2165.72 FB1.1@4946,2165.72
VSYNC: R22.1 U2.68 | length 590.8
  Top Layer w10: v1(4761,1765) 4761,1807 4831,1877 5064,1877 5104.32,1917.32 U2.68@5220.47,1917.32
  Bottom Layer w10: R22.1@4729.9,1736.75 4729.9,1738.25 4754.74,1763.09 4759.09,1763.09 v1(4761,1765)
VSYNC1: C12.1 J1.80 R22.2 | length 2273
  Bottom Layer w10: J1.80@2637.8,1708.66 2725.66,1708.66 2769,1752 3150,1752 3371,1973 3784,1973 3864,1893 4572.48,1893 4664.25,1801.23 C12.1@4665.75,1801.23 4729.38,1801.23 R22.2@4729.9,1801.75
WE2#: R11.2 U7.29 | length 129.9
  Top Layer w10: v1(3350,2289) U7.29@3350,2359.45
  Bottom Layer w10: R11.2@3344,2232 3350,2238 v1(3350,2289)
WE3#: R12.2 U7.28 | length 131.6
  Top Layer w10: U7.28@3400,2359.45 3400,2303.71 3409,2294.71 v1(3409,2292)
  Bottom Layer w10: v1(3409,2292) 3409,2233 R12.2@3410,2232
pads on no net: J1.27 J1.29 J1.31 J1.62 J1.64 J1.76 U2.51 U2.52 U2.71 U2.73 U2.74 U2.79 U2.82 U2.83 U2.84 U2.86 U2.87 U2.88 U2.89 U2.92 U2.93 U2.94 U2.95 U2.96 U2.127 U2.138 U2.141 U2.143 U2.157 U2.158 U7.11 U7.12 U7.15 U7.30 U20.1 U20.2 U20.30
copper on no net:
  other v2: 2509.84,903.54 2509.84,1746.06

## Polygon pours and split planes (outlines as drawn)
GND on Top Layer "NONET_L-01_P-001" (solid, remove dead copper, pour order 1): 2400.94,866.41 ccw(c2479.68,866.41) 2479.68,787.67 5274.95,787.67 ccw(c5274.95,866.41) 5353.69,866.41 5353.69,2559.32 ccw(c5274.95,2559.32) 5274.95,2638.06 2479.68,2638.06 ccw(c2479.68,2559.32) 2400.94,2559.32
GND on Bottom Layer "NONET_L-01_P-001" (solid, remove dead copper, pour order 0): 5353.69,2559.32 ccw(c5274.95,2559.32) 5274.95,2638.06 2479.68,2638.06 ccw(c2479.68,2559.32) 2400.94,2559.32 2400.94,866.41 ccw(c2479.68,866.41) 2479.68,787.67 5274.95,787.67 ccw(c5274.95,866.41) 5353.69,866.41

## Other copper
Top Layer:
  rectangle net VCC: 5159,2275 5214,2336
  region net VCC: 3913,2207 3872,2166 3872,1977 3853,1958 3853,1484 3854,1483 3886,1483 3894,1491 3894,1938 3909,1953 3909,2173 3925,2189 3925,2216 3925.27,2216.27
  region net VCC: 2609,1858 2553,1858 2545,1850 2545,1669 2526,1650 2526,1614 2534,1606 2546,1606 2554,1614 2554,1622 2564,1632 2587,1632 2662,1557 2711,1557 2721,1567 2721,1614 2700,1635 2654,1635 2609,1680 2609,1766
Bottom Layer:
  rectangle net VCC: 5004,946 5051,1066
  rectangle net VCC: 3885,2172 3927,2247
  rectangle net VCC: 3026,1877 3070,2017
  rectangle net VCC: 2780,1879 2826,2013
  rectangle net VCC: 2540,1812 2612,1873
  region net VCC: 2696,1621 2755,1621 2769,1607 2912,1607 2915,1604 2915,1570 2914,1569 2753,1569 2742,1558 2702,1558 2690,1570 2690,1609

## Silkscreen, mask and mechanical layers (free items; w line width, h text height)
Bottom Overlay:
  lines w8: 5066.93,803.15 5066.93,2622.05 5338.58,2350.39 ; 5066.93,1122.05 5338.58,850.39 ; 5066.93,1661.42 5342.52,1385.83 ; 5338.58,2350.39 5338.58,2350.39
Mechanical 1:
  the board outline again, w8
